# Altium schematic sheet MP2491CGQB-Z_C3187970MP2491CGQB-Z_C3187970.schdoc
size 127 x 101 mm
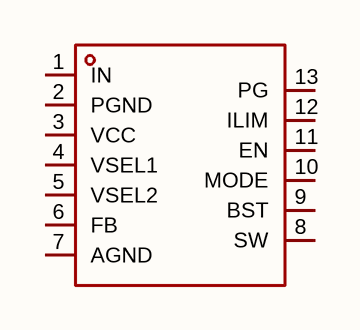
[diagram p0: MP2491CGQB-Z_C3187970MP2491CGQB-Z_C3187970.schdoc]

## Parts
U?  mp2491cgqb-z_c3187970  [QFN-13_L3.0-W2.5_MP2491C]  (value not drawn)

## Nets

Not connected (* = marked no-connect by the designer): U? 1(IN) 2(PGND) 3(VCC) 4(VSEL1) 5(VSEL2) 6(FB) 7(AGND) 8(SW) 9(BST) 10(MODE) 11(EN) 12(ILIM) 13(PG)

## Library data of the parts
U? = mp2491cgqb-z_c3187970: 功能类型:降压型;工作电压:4V~32V;输出电压:500mV~30V;输出电流:6A;输出类型:可调;; Manufacturer: MPS(芯源); AddInBom: yes; ModelId: 3e732ace16b942d3a543788565027af2; ModelTransform: 98.425,118.11,0,0,0,0,-7.874,0,0; Function: 降压型; Voltage - Supply: 4V~32V; Output Current: 6A; Frequency - Switching: 490kHz; Synchronous Rectifier: 是; Number of Outputs: 1; Topology: 降压式; Quiescent Current: 450uA; Switch tube (built-in/external): 内置; Output Type: 可调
